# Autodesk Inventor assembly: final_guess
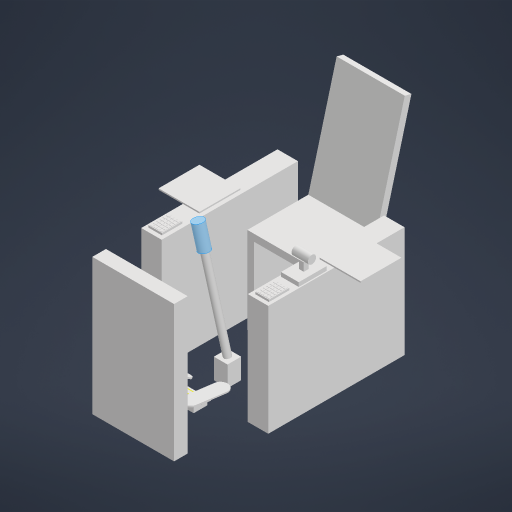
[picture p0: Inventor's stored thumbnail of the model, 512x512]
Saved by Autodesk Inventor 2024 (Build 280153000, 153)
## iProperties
Created: 2023-09
Part Number: final_guess
Document SubType Name: Assembly
Designer: mammothbane
Author: mammothbane
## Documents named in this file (13)
- \\caemlyn.p.hs.npry.dev\media\modeling\mit\mas.863\final_guess.iam
- \\caemlyn.p.hs.npry.dev\media\modeling\mit\mas.863\chair.ipt
- \\caemlyn.p.hs.npry.dev\media\modeling\mit\mas.863\joystick_block.ipt
- \\caemlyn.p.hs.npry.dev\media\modeling\mit\mas.863\base.ipt
- \\caemlyn.p.hs.npry.dev\media\modeling\mit\mas.863\arm.ipt
- \\caemlyn.p.hs.npry.dev\media\modeling\mit\mas.863\head.ipt
- \\caemlyn.p.hs.npry.dev\media\modeling\mit\mas.863\rudder_pedals.iam
- \\caemlyn.p.hs.npry.dev\media\modeling\mit\mas.863\front_panel.iam
- \\caemlyn.p.hs.npry.dev\media\modeling\mit\mas.863\walls.iam
- \\caemlyn.p.hs.npry.dev\media\modeling\mit\mas.863\front_wall.ipt
- \\caemlyn.p.hs.npry.dev\media\modeling\mit\mas.863\button_box.ipt
- \\caemlyn.p.hs.npry.dev\media\modeling\mit\mas.863\throttle.ipt
- \\caemlyn.p.hs.npry.dev\media\modeling\mit\mas.863\wing.ipt
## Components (14 placed, 12 different names)
1. chair:1 — joystick_bsae_planar, Planar:2, Flush:1
2. joystick_block:1
3. base:1 — joystick_ball_base, joystick_bsae_planar, Flush:2
4. arm:1 — joystick_head, joystick_ball_base
5. head:1 — joystick_head
6. rudder_pedals:1 [sub-assembly]
7. front_panel:1 [sub-assembly] — Planar:2, Planar:3
8. walls:1 [sub-assembly] — Flush:1, Flush:3, Planar:4, Flush:4, Flush:5, Planar:5
9. front_wall:1 — Flush:2, Planar:3
10. button_box:1 — Flush:3
11. button_box:2 — Planar:4
12. throttle:1 — Flush:4
13. wing:1 — Flush:5
14. wing:2 — Planar:5
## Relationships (12: PlanarJoint 5, Flush 5, WeldJoint 1, BallJoint 1)
- joystick_head [WeldJoint]: arm:1 ↔ head:1
- joystick_ball_base [BallJoint]: base:1 ↔ arm:1
- joystick_bsae_planar [PlanarJoint]: chair:1 ↔ base:1
- Planar:2: chair:1 ↔ front_panel:1
- Flush:1: chair:1 ↔ walls:1
- Flush:2: base:1 ↔ front_wall:1
- Planar:3: front_panel:1 ↔ front_wall:1
- Flush:3: walls:1 ↔ button_box:1
- Planar:4: walls:1 ↔ button_box:2
- Flush:4: walls:1 ↔ throttle:1
- Flush:5: walls:1 ↔ wing:1
- Planar:5: walls:1 ↔ wing:2
